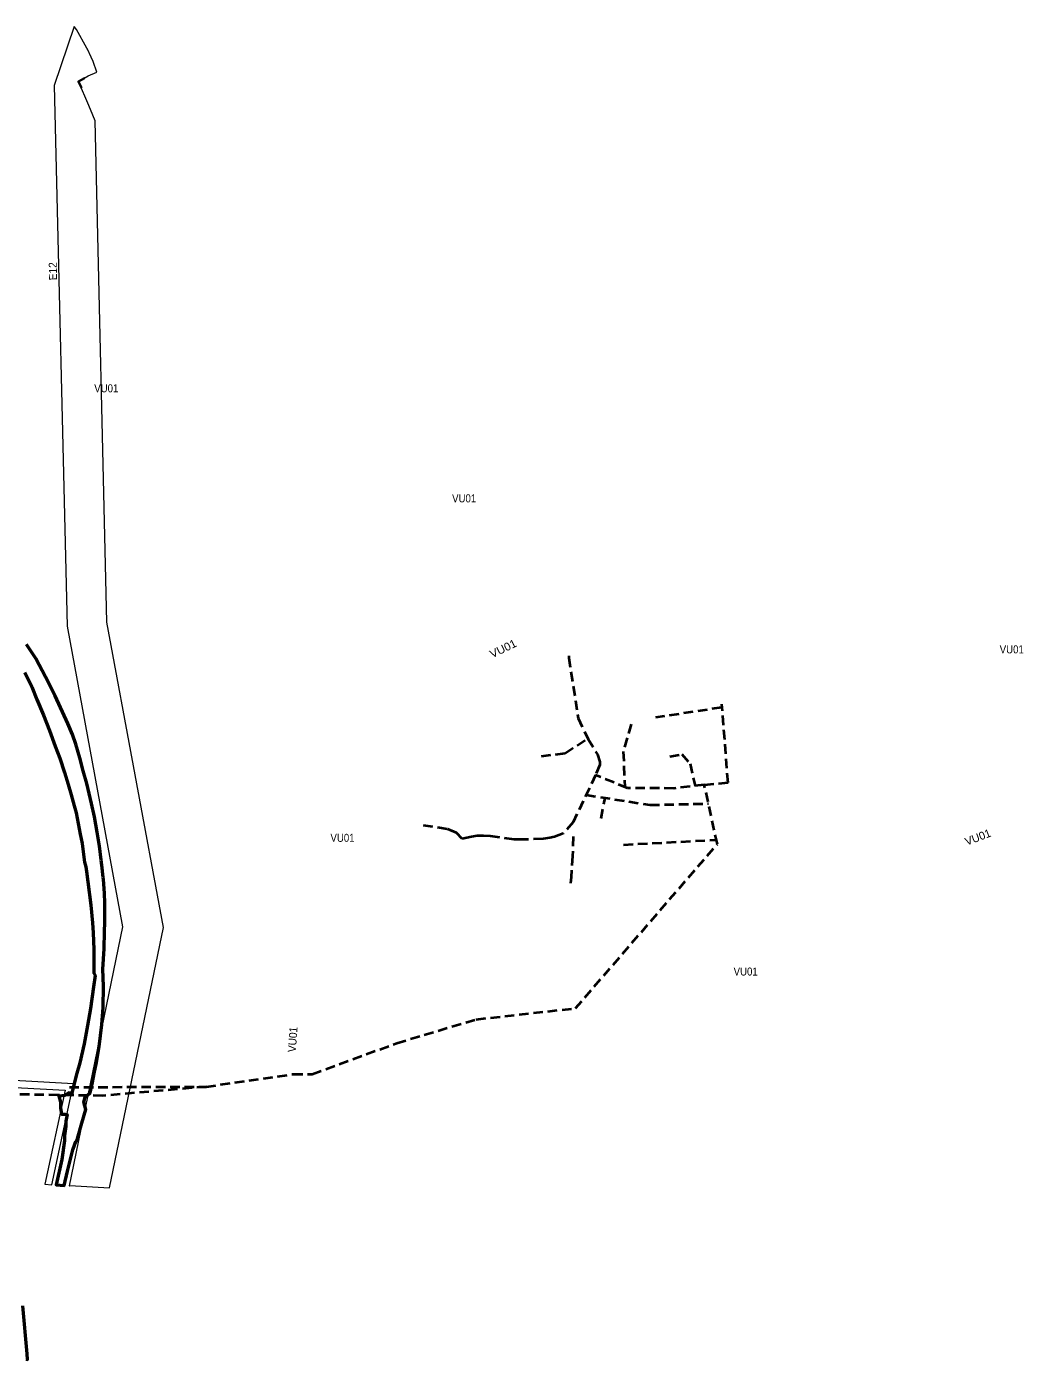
# Model space of a CAD drawing. Extents: x -650145 to -642675, y -1074338 to -1066724.
# Drawn here: x -645166 to -642675, y -1071415 to -1068085 of the extents above; entities that cross this region are included whole.
import ezdxf

# ---------------------------------------------------------------- set-up
doc = ezdxf.new("R2010")
doc.units = 0
doc.header["$LTSCALE"] = 8
doc.linetypes.add('MEDIUM_DASHED', pattern=[4.5, 3, -1.5])
for name, color, linetype, lineweight in [('12', 7, 'MEDIUM_DASHED', 40), ('15', 7, 'Continuous', 13), ('45', 7, 'Continuous', 53)]:
    doc.layers.add(name, color=color, linetype=linetype, lineweight=lineweight)
doc.layers.add('17', color=7, linetype='Continuous')
doc.layers.add('2', color=7, linetype='Continuous')

msp = doc.modelspace()

# ---------------------------------------------------------------- linework, layer by layer
at = {"layer": '12'}
for p, q in [((-643429.636, -1069786.459), (-643594.181, -1069811.599)), ((-643730.467, -1070063.614), (-643720.12, -1070012.253)), ((-643674.528, -1070129.34), (-643442.257, -1070116.937))]:
    msp.add_line(p, q, dxfattribs=at)
for points in [[(-643810.627, -1069657.665), (-643811.385, -1069662.021), (-643787.529, -1069813.369), (-643763.019, -1069865.538), (-643739.057, -1069904.105), (-643733.398, -1069922.453), (-643733.672, -1069929.3), (-643744.205, -1069955.268), (-643800.43, -1070073.069), (-643825.501, -1070101.354), (-643846.88, -1070109.266), (-643858.108, -1070112.46), (-643875.543, -1070114.925), (-643927.411, -1070116.568), (-643947.688, -1070115.858), (-644007.981, -1070107.962), (-644024.686, -1070106.729), (-644040.027, -1070107.201), (-644054.663, -1070109.432), (-644077.983, -1070114.354), (-644091.49, -1070099.721), (-644115.344, -1070090.018), (-644174.372, -1070081.528)], [(-645059.408, -1070735.063), (-644716.965, -1070734.034), (-644500.038, -1070702.585), (-644452.44, -1070702.66), (-644241.161, -1070625.072), (-644042.664, -1070565.642), (-643794.576, -1070538.041), (-643439.868, -1070127.812), (-643472.434, -1069979.54), (-643413.032, -1069974.132), (-643428.496, -1069777.693)], [(-643655.213, -1069827.906), (-643674.851, -1069896.398), (-643671.269, -1069984.982)], [(-643879.717, -1069908.04), (-643820.566, -1069900.574), (-643763.8, -1069863.876)], [(-643558.728, -1069909.08), (-643528.249, -1069902.841), (-643508.036, -1069927.391), (-643495.611, -1069982.269)], [(-643472.434, -1069979.54), (-643548.771, -1069988.527), (-643664.391, -1069987.784), (-643744.205, -1069955.268)], [(-643767.825, -1070004.757), (-643608.243, -1070029.834), (-643462.149, -1070026.369)], [(-643800.52, -1070109.14), (-643801.571, -1070157.278), (-643805.1, -1070210.207), (-643806.511, -1070225.027)], [(-644716.965, -1070734.034), (-644976.129, -1070756.486), (-645086.887, -1070754.876), (-645202.78, -1070753.267), (-645305.795, -1070754.34), (-645369.783, -1070785.657), (-645445.374, -1070804.496)]]:
    msp.add_lwpolyline(points, dxfattribs=at)
at = {"layer": '15'}
for points in [[(-645047.446, -1068085.007), (-645096.974, -1068231.922), (-645065.08, -1069583.124), (-644926.299, -1070334.854)], [(-644958.761, -1070986.696), (-644824.411, -1070335.926), (-644965.296, -1069572.802), (-644994.849, -1068320.753), (-645000.93, -1068306.11), (-645010.65, -1068282), (-645036.69, -1068221.92), (-645012.64, -1068208.23), (-644990.43, -1068198.75), (-644999.74, -1068171.88), (-645004.64, -1068161.3), (-645014.09, -1068140.85), (-645015.38, -1068138.59), (-645041.75, -1068092.48), (-645047.446, -1068085.007)], [(-644926.299, -1070334.854), (-645059.782, -1070981.425), (-645058.66, -1070981.49), (-645058.472, -1070980.896), (-644958.761, -1070986.696)], [(-645103.193, -1070978.912), (-645049.006, -1070727.131), (-645303.017, -1070712.927), (-645421.999, -1070689.793)], [(-645421.274, -1070707.252), (-645305.123, -1070729.835), (-645069.81, -1070742.995)], [(-645069.81, -1070742.995), (-645120.369, -1070977.92), (-645103.193, -1070978.912)]]:
    msp.add_lwpolyline(points, dxfattribs=at)
at = {"layer": '15', "lineweight": 35}
msp.add_lwpolyline([(-645029.39, -1068238.047), (-645036.69, -1068221.92), (-645021.142, -1068213.582)], dxfattribs=at)
at = {"layer": '45'}
for points in [[(-645170.3, -1069698.91), (-645153.44, -1069734.71), (-645140.27, -1069766.68), (-645123.84, -1069805.38), (-645108.74, -1069843.58), (-645094.42, -1069882.65), (-645083.31, -1069913.37), (-645071.53, -1069948.89), (-645062.57, -1069978.46), (-645054.73, -1070004.56), (-645047.28, -1070031.83), (-645042.27, -1070049.23), (-645032.21, -1070102.73), (-645027.49, -1070126.56), (-645021.14, -1070173.07), (-645018.56, -1070184.92), (-645016.92, -1070196.32), (-645013.51, -1070222.04), (-645005.98, -1070280.14), (-645001.81, -1070324.58), (-644999.47, -1070349.63), (-644997.87, -1070391.16), (-644998.17, -1070450.59), (-644995.14, -1070455.72), (-644998.92, -1070484.58), (-645006.44, -1070538.78), (-645014.07, -1070580.72), (-645022.64, -1070626.93), (-645033.53, -1070674.55), (-645041, -1070700.44), (-645046.63, -1070722.77), (-645053.21, -1070749.75), (-645060.46, -1070749.1), (-645065.17, -1070751.39), (-645070.3, -1070755.92), (-645085.58, -1070758.04), (-645081.75, -1070772.79), (-645081.85, -1070781.59), (-645081.13, -1070786.56), (-645078.85, -1070802.46), (-645070.2, -1070802.33), (-645065.01, -1070803.22), (-645068.07, -1070820.37), (-645068.52, -1070830.52), (-645068.07, -1070832.72), (-645071.18, -1070855.63), (-645071.77, -1070868.73), (-645078.23, -1070915.65), (-645092.67, -1070979.52), (-645071.99, -1070980.72), (-645064.39, -1070944.7), (-645050.47, -1070891.48), (-645045.74, -1070877.19), (-645043, -1070871.35), (-645039.25, -1070863.33), (-645028.25, -1070824.83), (-645018.18, -1070791.34), (-645023.25, -1070772.62), (-645019.57, -1070760.07), (-645007.68, -1070749.5), (-645001.71, -1070723.39), (-644997.14, -1070700.88), (-644992.6, -1070677.92), (-644985.04, -1070633.43), (-644978.44, -1070578.56), (-644975.05, -1070536.16), (-644974.44, -1070482.48), (-644975.29, -1070440.14), (-644972.48, -1070389.15), (-644971.37, -1070345.98), (-644970.61, -1070323.44), (-644970.36, -1070275.49), (-644971.47, -1070250.14), (-644974, -1070216.2), (-644974.49, -1070210.98), (-644978.49, -1070180.05), (-644979.57, -1070167.9), (-644984.21, -1070132.81), (-644989.62, -1070097.79), (-644996.88, -1070059.73), (-645004.02, -1070026.44), (-645016.01, -1069976.23), (-645024.45, -1069944.43), (-645032.85, -1069912.07), (-645043.5, -1069878.37), (-645051.78, -1069854.2), (-645063.26, -1069825.99), (-645095.1, -1069757.62), (-645118.98, -1069710.08), (-645143.56, -1069664.05), (-645153.33, -1069649.24), (-645166.67, -1069629)], [(-645167.37, -1071415.2), (-645163.56, -1071415.3), (-645164.76, -1071401.79), (-645175.4, -1071281.93)]]:
    msp.add_lwpolyline(points, dxfattribs=at)

# ---------------------------------------------------------------- texts
at = {"layer": '17', "width": 0.95}
msp.add_text('E12', height=20, rotation=90.939, dxfattribs=at).set_placement((-645090.224, -1068718.688))
at = {"layer": '2', "width": 0.9}
for p in [(-644997.156, -1068998.703), (-644102.761, -1069273.709), (-642734.104, -1069651.125), (-644406.791, -1070121.981), (-643399.108, -1070456.171)]:
    msp.add_text('VU01', height=20, dxfattribs=at).set_placement(p)
at = {"layer": '2'}
for rotation, width, p in [(25.964, 1.05, (-644002.392, -1069663.63)), (85.874, 0.95, (-644493.521, -1070648.37))]:
    msp.add_text('VU01', height=20, rotation=rotation, dxfattribs=dict(at, width=width)).set_placement(p)
msp.add_text('VU01', height=20, rotation=20.965, dxfattribs=at).set_placement((-642816.364, -1070131.907))

doc.saveas('drawing.dxf')
